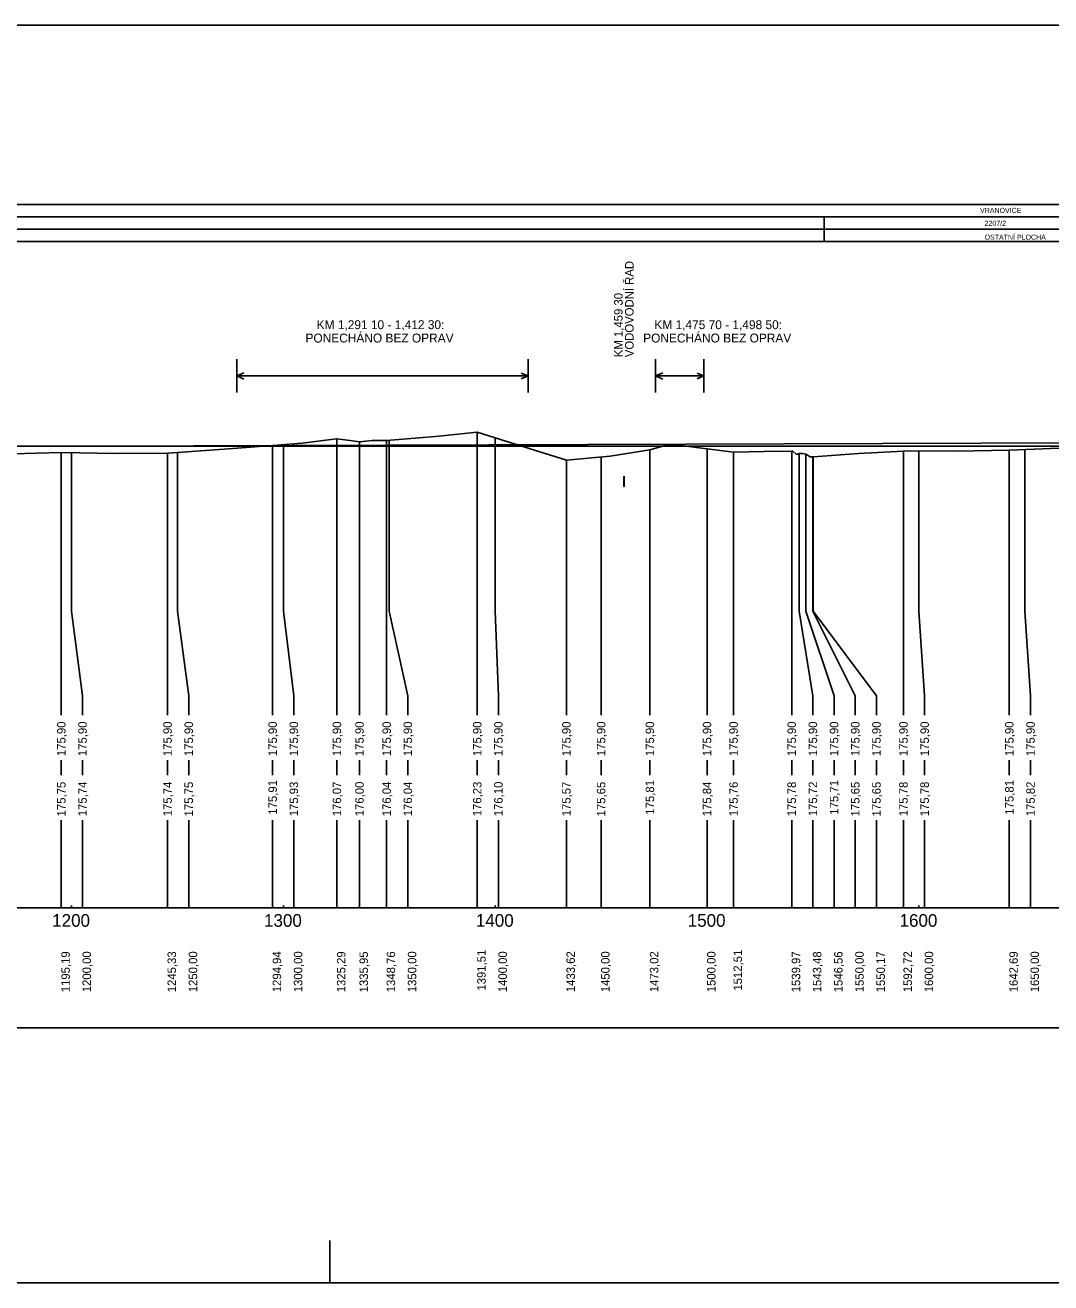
# Model space of a CAD drawing. Extents: x -614174 to -599765, y -1185887 to -1181080.
# Drawn here: x -612336 to -611852, y -1183382 to -1182788 of the extents above; entities that cross this region are included whole.
import ezdxf

# ---------------------------------------------------------------- set-up
doc = ezdxf.new("R2010")
doc.units = 0
for name, color, linetype in [('11', 7, 'Continuous'), ('13', 7, 'Continuous'), ('56', 7, 'Continuous'), ('Implicitní', 7, 'Continuous'), ('návrh', 7, 'Continuous')]:
    doc.layers.add(name, color=color, linetype=linetype)

msp = doc.modelspace()

# ---------------------------------------------------------------- linework, layer by layer
msp.add_line((-613514.51, -1182987.26), (-611402.58, -1182987.26))
for points in [[(-612342.33, -1182990.94), (-612319.32, -1182990.34), (-612319.19, -1182990.34), (-612293.77, -1182990.75), (-612269.18, -1182990.53), (-612268.9, -1182990.53), (-612242.5, -1182988.72), (-612219.56, -1182986.96), (-612219.48, -1182986.96), (-612205.68, -1182985.92), (-612189.37, -1182983.8), (-612189.22, -1182983.79), (-612184.18, -1182984.41), (-612178.62, -1182985.19), (-612178.56, -1182985.18), (-612172.63, -1182984.62), (-612165.75, -1182984.54), (-612165.75, -1182984.54), (-612142.62, -1182982.66), (-612123, -1182980.65), (-612123, -1182980.65), (-612100.99, -1182987.65), (-612080.89, -1182993.83), (-612080.8, -1182993.86), (-612060.3, -1182991.96), (-612041.55, -1182989.01), (-612041.49, -1182988.99), (-612034.22, -1182987.01), (-612025.55, -1182987.05), (-612002, -1182990.03), (-612001.88, -1182990.05), (-611987.75, -1182989.8), (-611974.54, -1182989.56), (-611974.15, -1182989.53), (-611972.24, -1182991.16), (-611971.02, -1182990.77), (-611970.77, -1182990.78), (-611969.49, -1182990.69), (-611968.08, -1182991.06), (-611967.95, -1182991.07), (-611965.75, -1182992.35), (-611964.34, -1182992.25), (-611964.25, -1182992.25), (-611943.08, -1182990.7), (-611921.78, -1182989.56), (-611921.68, -1182989.55), (-611896.68, -1182989.66), (-611871.81, -1182989.16), (-611871.77, -1182989.15), (-611848.49, -1182988.24)], [(-612123, -1182980.65), (-612123, -1183065.26), (-612123, -1183105.26), (-612123, -1183114.34)], [(-612214.51, -1182986.58), (-612214.51, -1183065.26), (-612209.56, -1183105.26), (-612209.56, -1183114.34)], [(-612189.22, -1182983.79), (-612189.22, -1183065.26), (-612189.22, -1183105.26), (-612189.22, -1183114.34)], [(-612178.56, -1182985.18), (-612178.56, -1183065.26), (-612178.56, -1183105.26), (-612178.56, -1183114.34)], [(-612165.75, -1182984.54), (-612165.75, -1183065.26), (-612165.75, -1183105.26), (-612165.75, -1183114.34)], [(-612164.51, -1182984.44), (-612164.51, -1183065.26), (-612155.75, -1183105.26), (-612155.75, -1183114.34)], [(-612114.51, -1182983.35), (-612114.51, -1183065.26), (-612113, -1183105.26), (-612113, -1183114.34)], [(-612319.32, -1182990.34), (-612319.32, -1183065.26), (-612319.32, -1183105.26), (-612319.32, -1183114.34)], [(-612314.51, -1182990.41), (-612314.51, -1183065.26), (-612309.32, -1183105.26), (-612309.32, -1183114.34)], [(-612269.18, -1182990.53), (-612269.18, -1183065.26), (-612269.18, -1183105.26), (-612269.18, -1183114.34)], [(-612264.51, -1182990.23), (-612264.51, -1183065.26), (-612259.18, -1183105.26), (-612259.18, -1183114.34)], [(-612219.56, -1182986.96), (-612219.56, -1183065.26), (-612219.56, -1183105.26), (-612219.56, -1183114.34)], [(-612064.51, -1182992.35), (-612064.51, -1183065.26), (-612064.51, -1183105.26), (-612064.51, -1183114.34)], [(-612041.49, -1182988.99), (-612041.49, -1183065.26), (-612041.49, -1183105.26), (-612041.49, -1183114.34)], [(-612014.51, -1182988.45), (-612014.51, -1183065.26), (-612014.51, -1183105.26), (-612014.51, -1183114.34)], [(-612002, -1182990.03), (-612002, -1183065.26), (-612002, -1183105.26), (-612002, -1183114.34)], [(-611974.54, -1182989.56), (-611974.54, -1183065.26), (-611974.54, -1183105.26), (-611974.54, -1183114.34)], [(-611971.02, -1182990.77), (-611971.02, -1183065.26), (-611964.54, -1183105.26), (-611964.54, -1183114.34)], [(-611967.95, -1182991.07), (-611967.95, -1183065.26), (-611954.54, -1183105.26), (-611954.54, -1183114.34)], [(-611964.51, -1182992.26), (-611964.51, -1183065.26), (-611944.54, -1183105.26), (-611944.54, -1183114.34)], [(-611964.34, -1182992.25), (-611964.34, -1183065.26), (-611934.54, -1183105.26), (-611934.54, -1183114.34)], [(-611921.78, -1182989.56), (-611921.78, -1183065.26), (-611921.78, -1183105.26), (-611921.78, -1183114.34)], [(-611914.51, -1182989.58), (-611914.51, -1183065.26), (-611911.78, -1183105.26), (-611911.78, -1183114.34)], [(-611871.81, -1182989.16), (-611871.81, -1183065.26), (-611871.81, -1183105.26), (-611871.81, -1183114.34)], [(-611864.51, -1182988.87), (-611864.51, -1183065.26), (-611861.81, -1183105.26), (-611861.81, -1183114.34)], [(-612080.89, -1182993.83), (-612080.89, -1183065.26), (-612080.89, -1183105.26), (-612080.89, -1183114.34)], [(-612319.32, -1183135.54), (-612319.32, -1183142.7)], [(-612309.32, -1183135.54), (-612309.32, -1183142.7)], [(-612269.18, -1183135.54), (-612269.18, -1183142.7)], [(-612259.18, -1183135.54), (-612259.18, -1183142.7)], [(-612219.56, -1183135.54), (-612219.56, -1183142.7)], [(-612209.56, -1183135.54), (-612209.56, -1183142.7)], [(-612189.22, -1183135.54), (-612189.22, -1183142.7)], [(-612178.56, -1183135.54), (-612178.56, -1183142.7)], [(-612165.75, -1183135.54), (-612165.75, -1183142.7)], [(-612155.75, -1183135.54), (-612155.75, -1183142.7)], [(-612123, -1183135.54), (-612123, -1183142.7)], [(-612113, -1183135.54), (-612113, -1183142.7)], [(-612080.89, -1183135.54), (-612080.89, -1183142.7)], [(-612064.51, -1183135.54), (-612064.51, -1183142.7)], [(-612041.49, -1183135.54), (-612041.49, -1183142.7)], [(-612014.51, -1183135.54), (-612014.51, -1183142.7)], [(-612002, -1183135.54), (-612002, -1183142.7)], [(-611974.54, -1183135.54), (-611974.54, -1183142.7)], [(-611964.54, -1183135.54), (-611964.54, -1183142.7)], [(-611954.54, -1183135.54), (-611954.54, -1183142.7)], [(-611944.54, -1183135.54), (-611944.54, -1183142.7)], [(-611934.54, -1183135.54), (-611934.54, -1183142.7)], [(-611921.78, -1183135.54), (-611921.78, -1183142.7)], [(-611911.78, -1183135.54), (-611911.78, -1183142.7)], [(-611871.81, -1183135.54), (-611871.81, -1183142.7)], [(-611861.81, -1183135.54), (-611861.81, -1183142.7)], [(-612319.32, -1183163.91), (-612319.32, -1183205.26)], [(-612309.32, -1183163.91), (-612309.32, -1183205.26)], [(-612269.18, -1183163.91), (-612269.18, -1183205.26)], [(-612259.18, -1183163.91), (-612259.18, -1183205.26)], [(-612219.56, -1183163.91), (-612219.56, -1183205.26)], [(-612209.56, -1183163.91), (-612209.56, -1183205.26)], [(-612189.22, -1183163.91), (-612189.22, -1183205.26)], [(-612178.56, -1183163.91), (-612178.56, -1183205.26)], [(-612165.75, -1183163.91), (-612165.75, -1183205.26)], [(-612155.75, -1183163.91), (-612155.75, -1183205.26)], [(-612123, -1183163.91), (-612123, -1183205.26)], [(-612113, -1183163.91), (-612113, -1183205.26)], [(-612080.89, -1183163.91), (-612080.89, -1183205.26)], [(-612064.51, -1183163.91), (-612064.51, -1183205.26)], [(-612041.49, -1183163.91), (-612041.49, -1183205.26)], [(-612014.51, -1183163.91), (-612014.51, -1183205.26)], [(-612002, -1183163.91), (-612002, -1183205.26)], [(-611974.54, -1183163.91), (-611974.54, -1183205.26)], [(-611964.54, -1183163.91), (-611964.54, -1183205.26)], [(-611954.54, -1183163.91), (-611954.54, -1183205.26)], [(-611944.54, -1183163.91), (-611944.54, -1183205.26)], [(-611934.54, -1183163.91), (-611934.54, -1183205.26)], [(-611921.78, -1183163.91), (-611921.78, -1183205.26)], [(-611911.78, -1183163.91), (-611911.78, -1183205.26)], [(-611871.81, -1183163.91), (-611871.81, -1183205.26)], [(-611861.81, -1183163.91), (-611861.81, -1183205.26)], [(-613514.51, -1183261.99), (-611395.59, -1183261.99)]]:
    msp.add_lwpolyline(points)
at = {"layer": '56'}
for p, q in [((-613514.51, -1183205.26), (-611314.51, -1183205.26)), ((-612314.51, -1183205.26), (-612314.51, -1183204.26)), ((-612214.51, -1183205.26), (-612214.51, -1183204.26)), ((-612114.51, -1183205.26), (-612114.51, -1183204.26)), ((-612014.51, -1183205.26), (-612014.51, -1183204.26)), ((-611914.51, -1183205.26), (-611914.51, -1183204.26))]:
    msp.add_line(p, q, dxfattribs=at)
at = {"layer": 'návrh'}
for p, q in [((-613657.4, -1182788.43), (-610932.51, -1182788.43)), ((-611959.21, -1182879), (-611959.21, -1182890.67)), ((-612236.5, -1182961.98), (-612236.5, -1182946.2)), ((-612099.01, -1182961.98), (-612099.01, -1182946.2)), ((-612038.8, -1182961.98), (-612038.8, -1182946.2)), ((-612016, -1182961.98), (-612016, -1182946.2)), ((-612236.5, -1182954.09), (-612233.13, -1182952.64)), ((-612236.5, -1182954.09), (-612233.09, -1182955.65)), ((-612236.5, -1182954.09), (-612099.01, -1182954.09)), ((-612099.01, -1182954.09), (-612102.19, -1182952.85)), ((-612099.01, -1182954.09), (-612102.19, -1182955.45)), ((-612038.8, -1182954.09), (-612035.43, -1182952.64)), ((-612038.8, -1182954.09), (-612035.39, -1182955.65)), ((-612038.8, -1182954.09), (-612016, -1182954.09)), ((-612016, -1182954.09), (-612019.18, -1182952.85)), ((-612016, -1182954.09), (-612019.18, -1182955.45)), ((-611394.51, -1182984.06), (-613514.51, -1182991.66)), ((-612192.51, -1183362.43), (-612192.51, -1183382.43)), ((-613452.51, -1183382.43), (-610932.51, -1183382.43))]:
    msp.add_line(p, q, dxfattribs=at)
for points in [[(-613514.51, -1182873.17), (-611398.36, -1182873.17), (-611398.36, -1182879), (-613514.51, -1182879)], [(-613514.51, -1182879), (-611398.36, -1182879), (-611398.36, -1182884.84), (-613514.51, -1182884.84)], [(-613514.51, -1182884.84), (-611398.36, -1182884.84), (-611398.36, -1182890.67), (-613514.51, -1182890.67)]]:
    msp.add_lwpolyline(points, close=True, dxfattribs=at)
msp.add_ellipse((-612053.7, -1183003.87), major_axis=(0, 2.5), ratio=0.05, dxfattribs=at)

# ---------------------------------------------------------------- texts
at = {"layer": '11'}
for s, p in [('175,90', (-612317.32, -1183133.67)), ('175,90', (-612307.32, -1183133.67)), ('175,90', (-612267.18, -1183133.67)), ('175,90', (-612257.18, -1183133.67)), ('175,90', (-612217.56, -1183133.67)), ('175,90', (-612207.56, -1183133.67)), ('175,90', (-612187.22, -1183133.67)), ('175,90', (-612176.56, -1183133.67)), ('175,90', (-612163.75, -1183133.67)), ('175,90', (-612153.75, -1183133.67)), ('175,90', (-612121, -1183133.67)), ('175,90', (-612111, -1183133.67)), ('175,90', (-612078.89, -1183133.67)), ('175,90', (-612062.51, -1183133.67)), ('175,90', (-612039.49, -1183133.67)), ('175,90', (-612012.51, -1183133.67)), ('175,90', (-612000, -1183133.67)), ('175,90', (-611972.54, -1183133.67)), ('175,90', (-611962.54, -1183133.67)), ('175,90', (-611952.54, -1183133.67)), ('175,90', (-611942.54, -1183133.67)), ('175,90', (-611932.54, -1183133.67)), ('175,90', (-611919.78, -1183133.67)), ('175,90', (-611909.78, -1183133.67)), ('175,90', (-611869.81, -1183133.67)), ('175,90', (-611859.81, -1183133.67)), ('175,75', (-612317.32, -1183162.12)), ('175,74', (-612307.32, -1183162.07)), ('175,74', (-612267.18, -1183162.07)), ('175,75', (-612257.18, -1183162.12)), ('175,91', (-612217.56, -1183161.32)), ('175,93', (-612207.56, -1183162.09)), ('176,07', (-612187.22, -1183162.09)), ('176,00', (-612176.56, -1183162.07)), ('176,04', (-612163.75, -1183162.07)), ('176,04', (-612153.75, -1183162.07)), ('176,23', (-612121, -1183162.09)), ('176,10', (-612111, -1183162.07)), ('175,57', (-612078.89, -1183162.09)), ('175,65', (-612062.51, -1183162.12)), ('175,81', (-612039.49, -1183161.32)), ('175,84', (-612012.51, -1183162.07)), ('175,76', (-612000, -1183162.09)), ('175,78', (-611972.54, -1183162.1)), ('175,72', (-611962.54, -1183162.05)), ('175,71', (-611952.54, -1183161.32)), ('175,65', (-611942.54, -1183162.12)), ('175,65', (-611932.54, -1183162.12)), ('175,78', (-611919.78, -1183162.1)), ('175,78', (-611909.78, -1183162.1)), ('175,81', (-611869.81, -1183161.32)), ('175,82', (-611859.81, -1183162.05)), ('1195,19', (-612315.32, -1183245.2)), ('1200,00', (-612305.32, -1183245.18)), ('1245,33', (-612265.18, -1183245.2)), ('1250,00', (-612255.18, -1183245.18)), ('1294,94', (-612215.56, -1183245.18)), ('1300,00', (-612205.56, -1183245.18)), ('1325,29', (-612185.22, -1183245.2)), ('1335,95', (-612174.56, -1183245.23)), ('1348,76', (-612161.75, -1183245.2)), ('1350,00', (-612151.75, -1183245.18)), ('1391,51', (-612119, -1183244.42)), ('1400,00', (-612109, -1183245.18)), ('1433,62', (-612076.89, -1183245.15)), ('1450,00', (-612060.51, -1183245.18)), ('1473,02', (-612037.49, -1183245.15)), ('1500,00', (-612010.51, -1183245.18)), ('1512,51', (-611998, -1183244.42)), ('1539,97', (-611970.54, -1183245.2)), ('1543,48', (-611960.54, -1183245.2)), ('1546,56', (-611950.54, -1183245.2)), ('1550,00', (-611940.54, -1183245.18)), ('1550,17', (-611930.54, -1183245.2)), ('1592,72', (-611917.78, -1183245.15)), ('1600,00', (-611907.78, -1183245.18)), ('1642,69', (-611867.81, -1183245.2)), ('1650,00', (-611857.81, -1183245.18))]:
    msp.add_text(s, height=4, rotation=90, dxfattribs=at).set_placement(p)
at = {"layer": '13'}
for s, height, p in [('VRANOVICE', 2.4, (-611885.63, -1182877.11)), ('2207/2', 2.4, (-611883.5, -1182883.21)), ('OSTATNÍ PLOCHA', 2.4, (-611883.5, -1182889.76)), ('PONECHÁNO BEZ OPRAV', 4.2, (-612204.06, -1182938.3)), ('KM 1,291 10 - 1,412 30: ', 4.2, (-612198.77, -1182932)), ('PONECHÁNO BEZ OPRAV', 4.2, (-612044.65, -1182938.3)), ('KM 1,475 70 - 1,498 50: ', 4.2, (-612039.36, -1182932)), ('1200', 6, (-612323.63, -1183214.26)), ('1300', 6, (-612223.63, -1183214.26)), ('1400', 6, (-612123.63, -1183214.26)), ('1500', 6, (-612023.63, -1183214.26)), ('1600', 6, (-611923.63, -1183214.26))]:
    msp.add_text(s, height=height, dxfattribs=at).set_placement(p)
at = {"layer": 'Implicitní'}
for s, p in [('VODOVODNÍ ŘAD ', (-612049.19, -1182945.25)), ('KM 1,459 30  ', (-612054.36, -1182945.25))]:
    msp.add_text(s, height=4, rotation=90, dxfattribs=at).set_placement(p)

doc.saveas('drawing.dxf')
